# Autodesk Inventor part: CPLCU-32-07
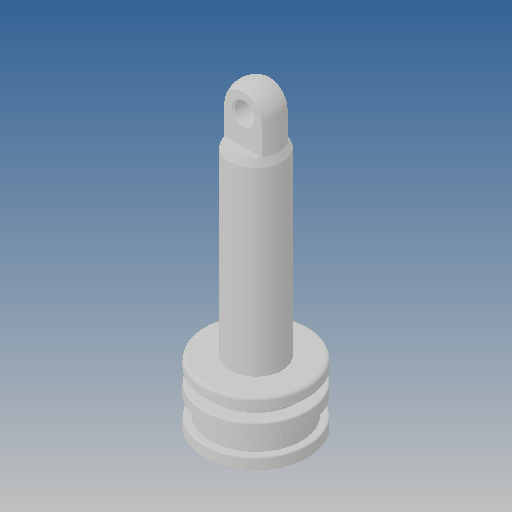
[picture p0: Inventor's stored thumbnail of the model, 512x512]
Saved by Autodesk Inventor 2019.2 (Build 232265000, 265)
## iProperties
Created: 2010-03
Part Number: CPLCU-32-07
Material: Ogólny
Document SubType Name: Modeling
Designer: CADENGINEERING4
Density: 1 g/cm^3
Appearance: Domyślna
Author: CADENGINEERING4
Revision Number: 1LAST_VERSION
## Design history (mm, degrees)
feature "Baza1"
node "Bryła1"
